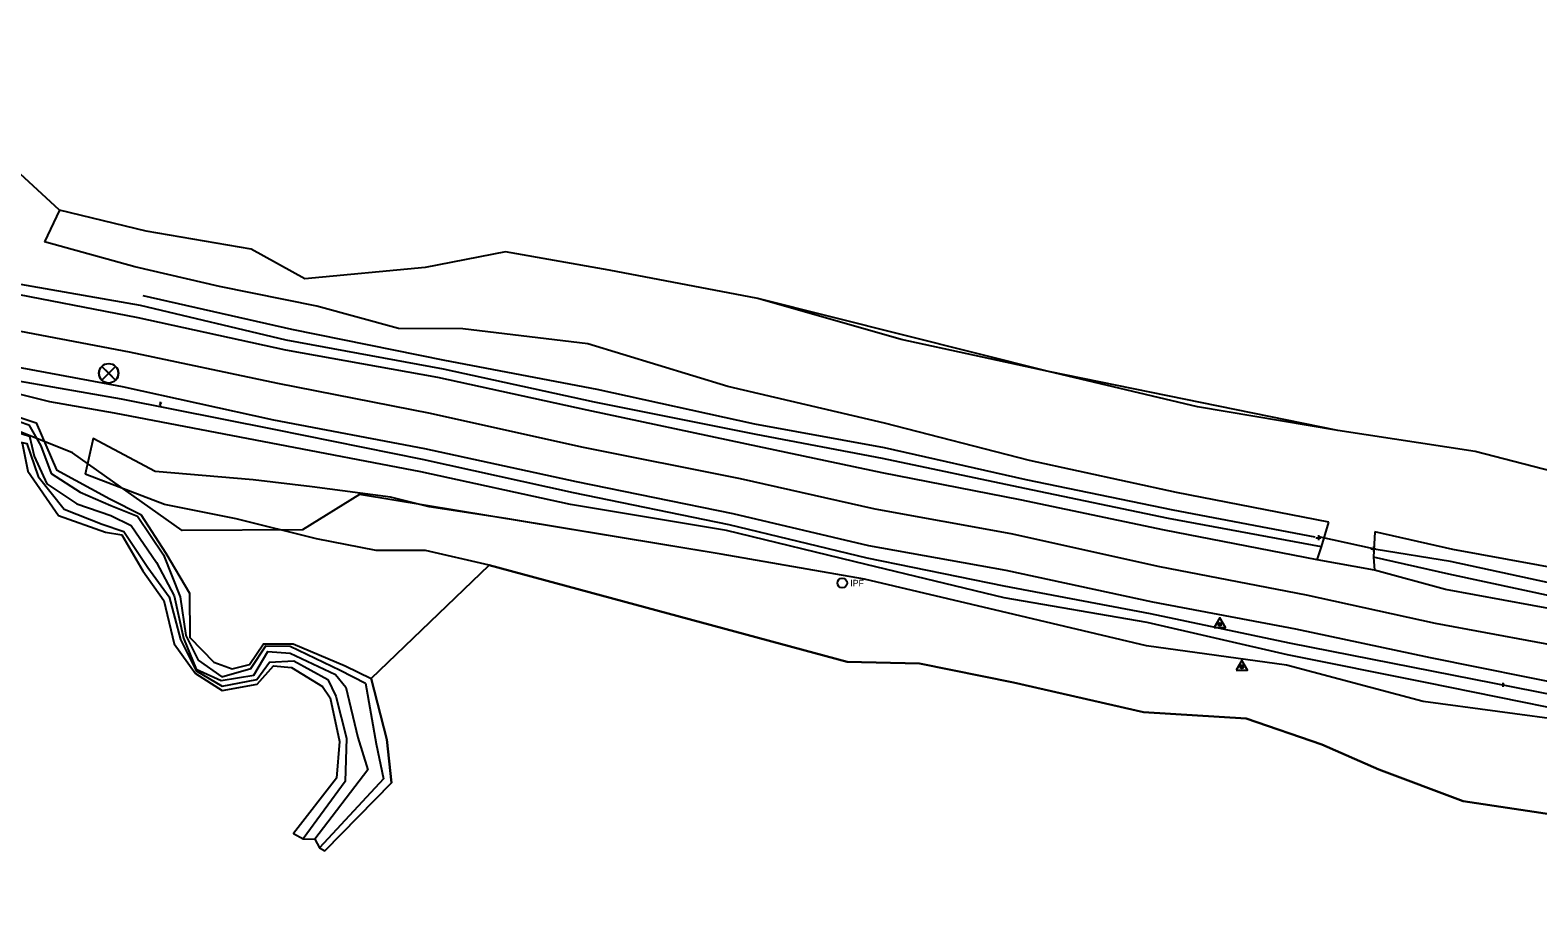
# Model space of a CAD drawing. Extents: x 1158469 to 1165378, y 609843 to 611748.
# Drawn here: x 1161265 to 1161728.7, y 610709.6 to 610983.5 of the extents above; entities that cross this region are included whole.
import ezdxf

# ---------------------------------------------------------------- set-up
doc = ezdxf.new("R2010")
doc.units = 0
for name, color, linetype in [('Exterior Boundary', 7, 'Continuous'), ('S_Control_Temp_Traverse', 7, 'Continuous'), ('S_Control_Traverse_Point', 7, 'Continuous'), ('S_Drainage_Culvert_Top', 7, 'Continuous'), ('S_Drainage_Ditch_Line', 7, 'Continuous'), ('S_Drainage_Invert', 7, 'Continuous'), ('S_Drainage_Waterway', 7, 'Continuous'), ('S_Ground_Elevation', 7, 'Continuous'), ('S_Ground_SpotElevation', 7, 'Continuous'), ('S_Property_IronPipeFound', 7, 'Continuous'), ('S_Roadway_Centerline', 7, 'Continuous'), ('S_Roadway_Edge_Pavement', 7, 'Continuous'), ('S_Roadway_Entr_Field_Wood', 7, 'Continuous'), ('S_Trees_TreeLine', 7, 'Continuous'), ('S_Utilities_UG_BoringLocation', 7, 'Continuous')]:
    doc.layers.add(name, color=color, linetype=linetype)

msp = doc.modelspace()

# ---------------------------------------------------------------- linework, layer by layer
at = {"layer": 'Exterior Boundary'}
for points in [[(1161754.22, 610842.36), (1161709.38, 610853.89), (1161667.17, 610860.36), (1161578.14, 610878.5), (1161488.83, 610900.92), (1161443.04, 610909.71), (1161411.18, 610915.31), (1161386.43, 610910.46), (1161349.48, 610906.98), (1161332.93, 610916.14), (1161300.61, 610921.61), (1161274, 610928.1), (1161260.61, 610940.47)], [(1161264.24, 610847.8), (1161273.73, 610834.24), (1161288.14, 610829.07), (1161293.19, 610828.3), (1161299.67, 610817.24), (1161306.08, 610808.09), (1161309.31, 610794.78), (1161315.87, 610785.65), (1161323.99, 610780.43), (1161334.82, 610782.31), (1161339.83, 610787.96), (1161345.36, 610787.46), (1161354.85, 610781.64), (1161357.27, 610778.1), (1161360.15, 610764.72), (1161359.24, 610753.43), (1161346, 610736.46), (1161348.98, 610734.8), (1161352.57, 610734.7), (1161353.93, 610731.98), (1161355.59, 610731.11), (1161376.09, 610752.03), (1161374.73, 610765.32), (1161369.82, 610784.14), (1161406.17, 610818.99), (1161516.3, 610789.17), (1161538.56, 610788.68), (1161567.46, 610782.86), (1161607.39, 610773.7), (1161638.99, 610771.82), (1161662.23, 610763.76), (1161679.82, 610756.1), (1161705.72, 610746.36), (1161737.12, 610741.7)]]:
    msp.add_lwpolyline(points, dxfattribs=at)
at = {"layer": 'S_Control_Temp_Traverse'}
for p, q in [((1161637.53, 610787.65), (1161637.78, 610787.65)), ((1161637.65, 610787.77), (1161637.65, 610787.52))]:
    msp.add_line(p, q, dxfattribs=at)
msp.add_lwpolyline([(1161635.92, 610786.65), (1161639.38, 610786.65), (1161637.65, 610789.65)], close=True, dxfattribs=at)
msp.add_circle((1161637.65, 610787.65), 0.5, dxfattribs=at)
at = {"layer": 'S_Control_Traverse_Point'}
for p, q in [((1161630.73, 610800.75), (1161630.98, 610800.75)), ((1161630.85, 610800.87), (1161630.85, 610800.62))]:
    msp.add_line(p, q, dxfattribs=at)
msp.add_lwpolyline([(1161629.12, 610799.75), (1161632.58, 610799.75), (1161630.85, 610802.75)], close=True, dxfattribs=at)
msp.add_circle((1161630.85, 610800.75), 0.5, dxfattribs=at)
at = {"layer": 'S_Drainage_Culvert_Top'}
msp.add_lwpolyline([(1161678.1, 610823.99), (1161661.34, 610827.65)], dxfattribs=at)
at = {"layer": 'S_Drainage_Ditch_Line'}
for points in [[(1161240.49, 610874.37), (1161240.56, 610869.57), (1161246.38, 610861.53), (1161256.4, 610861.31), (1161264.81, 610858.62), (1161266.17, 610852.48), (1161270.08, 610844), (1161279.35, 610837.83), (1161289.8, 610834.22), (1161296.09, 610831.16), (1161303.82, 610819.81), (1161309.31, 610809.5), (1161312.11, 610796.45), (1161315.99, 610787.01), (1161323.7, 610783.5), (1161333.78, 610785.14), (1161338.11, 610792.4), (1161344.91, 610791.9), (1161358.91, 610785.33)], [(1161362.12, 610781.47), (1161365.74, 610765.98), (1161368.83, 610756.03), (1161352.57, 610734.7)], [(1161358.91, 610785.33), (1161362.12, 610781.47)]]:
    msp.add_lwpolyline(points, dxfattribs=at)
at = {"layer": 'S_Drainage_Invert'}
for p, q in [((1161661.18, 610828.14), (1161661.18, 610826.64)), ((1161660.43, 610827.39), (1161661.93, 610827.39)), ((1161677.37, 610823.94), (1161678.87, 610823.94)), ((1161678.12, 610824.69), (1161678.12, 610823.19))]:
    msp.add_line(p, q, dxfattribs=at)
at = {"layer": 'S_Drainage_Waterway'}
for points in [[(1161241.67, 610874.19), (1161242.6, 610872.08), (1161249.22, 610866.27), (1161251.97, 610864.37), (1161258.63, 610864.13), (1161264.58, 610862.05), (1161268.3, 610855.69), (1161271.43, 610847.12), (1161280.38, 610841.38), (1161289.78, 610837.31), (1161298.01, 610833.99), (1161305.99, 610822.11), (1161311.15, 610809.24), (1161312.89, 610797.29), (1161316.7, 610789.69), (1161323.91, 610784.64), (1161332.81, 610787.12), (1161337.5, 610794.15), (1161344.91, 610794.02), (1161360.33, 610786.66)], [(1161236.73, 610873.49), (1161231.05, 610865.68), (1161230.05, 610852.4), (1161238.89, 610845.87), (1161249.62, 610853.15), (1161253.15, 610858.65), (1161263.99, 610856.33), (1161267.43, 610846.26), (1161275.39, 610836.13), (1161287.11, 610831.52), (1161293.84, 610829.29), (1161301.12, 610818.22), (1161307.71, 610809.22), (1161311.17, 610796.1), (1161316.07, 610786.42), (1161324.07, 610781.74), (1161334.71, 610783.77), (1161338.57, 610789.12), (1161346.06, 610789.51), (1161356.52, 610783.79)], [(1161360.33, 610786.66), (1161368.09, 610782.69)], [(1161368.09, 610782.69), (1161371.41, 610764.01), (1161373.64, 610753.23), (1161353.93, 610731.98)], [(1161356.52, 610783.79), (1161359.01, 610778.62)], [(1161359.01, 610778.62), (1161362.25, 610765.77), (1161361.86, 610752.43), (1161348.98, 610734.8)]]:
    msp.add_lwpolyline(points, dxfattribs=at)
at = {"layer": 'S_Ground_Elevation'}
for points in [[(1161662.12, 610824.6), (1161615.06, 610833.28), (1161570.93, 610842.51), (1161527.13, 610851.74), (1161488.26, 610859.12), (1161438.51, 610869.06), (1161392.1, 610879.17), (1161343.75, 610888.14), (1161298.92, 610898.79), (1161253.81, 610906.66), (1161217.92, 610914.01), (1161165.93, 610924.97), (1161116.75, 610934.27), (1161070.84, 610943.29), (1161018.86, 610953.77), (1160967.67, 610963.93), (1160913.31, 610974.22), (1160868.61, 610983.47)], [(1161790.92, 610767.7), (1161652.32, 610794.96), (1161609.52, 610803.98), (1161564.52, 610812.47), (1161522.37, 610821.13), (1161479.95, 610831.35), (1161432.13, 610841.23), (1161385.7, 610851.45), (1161340.05, 610860.71), (1161293.11, 610869.99), (1161250.75, 610877.37), (1161240.69, 610879.27), (1161216.11, 610885.09), (1161159.96, 610896.24), (1161111.51, 610906.19), (1161066.23, 610915.77), (1161015.8, 610925.93), (1160960.56, 610937.24), (1160907.14, 610946.59), (1160863.4, 610954.65)], [(1161754.22, 610842.36), (1161709.38, 610853.89), (1161667.17, 610860.36), (1161624.05, 610867.65), (1161578.14, 610878.5), (1161532.89, 610888.32), (1161488.83, 610900.92), (1161443.04, 610909.71), (1161411.18, 610915.31), (1161386.43, 610910.46), (1161349.48, 610906.98), (1161332.93, 610916.14), (1161300.61, 610921.61), (1161274, 610928.1), (1161269.34, 610918.39)], [(1161664.39, 610832.2), (1161617.51, 610841.34), (1161572.32, 610851.08), (1161527.76, 610862.6), (1161479.58, 610873.9), (1161436.47, 610886.98), (1161398.01, 610891.58), (1161378.28, 610891.77), (1161353.14, 610898.64), (1161323.21, 610904.64), (1161297.19, 610910.71), (1161269.34, 610918.39)], [(1161660.16, 610827.58), (1161616.5, 610835.81), (1161571.29, 610845.22), (1161527.78, 610855.04), (1161487.82, 610862.27), (1161439.38, 610872.93), (1161392.54, 610881.93), (1161345.45, 610891.42), (1161299.73, 610901.82)], [(1161738.64, 610773.86), (1161694.09, 610782.91), (1161651.67, 610791.38), (1161608.53, 610801.35), (1161564.59, 610808.93), (1161522.13, 610819.16), (1161479.19, 610829.62), (1161431.14, 610837.59), (1161385.12, 610847.66), (1161339.14, 610856.48), (1161290.9, 610865.68), (1161270.98, 610869.16), (1161250.36, 610874.26)], [(1161256.85, 610865.96), (1161266.85, 610862.75), (1161273.06, 610848.21), (1161289.46, 610839.3), (1161299.04, 610834.49), (1161306.69, 610822.59), (1161313.99, 610810.35), (1161314.13, 610796.73), (1161321.42, 610789.12), (1161327.13, 610787.06), (1161332.4, 610788.39), (1161336.74, 610794.78), (1161345.85, 610794.8), (1161361.85, 610788.01)], [(1161254.29, 610857.8), (1161262.53, 610856.53), (1161264.24, 610847.8), (1161273.73, 610834.24), (1161288.14, 610829.07), (1161293.19, 610828.3), (1161299.67, 610817.24), (1161306.08, 610808.09), (1161309.31, 610794.78), (1161315.87, 610785.65), (1161323.99, 610780.43), (1161334.82, 610782.31), (1161339.83, 610787.96), (1161345.36, 610787.46), (1161354.85, 610781.64)], [(1161739.1, 610770.82), (1161693.43, 610777.05), (1161651.4, 610788.18), (1161608.37, 610794.12), (1161563.73, 610804.71), (1161521.61, 610814.64), (1161477.5, 610822.28), (1161411.23, 610833.32), (1161387.71, 610836.93), (1161375.8, 610839.85), (1161351.69, 610843.04), (1161333.57, 610845.2), (1161303.44, 610847.76), (1161284.38, 610857.9), (1161281.94, 610846.96)], [(1161737.12, 610741.7), (1161705.72, 610746.36), (1161679.82, 610756.1), (1161662.23, 610763.76), (1161638.99, 610771.82), (1161607.39, 610773.7), (1161567.46, 610782.86), (1161538.56, 610788.68), (1161516.3, 610789.17), (1161406.17, 610818.99), (1161386.62, 610823.41), (1161371.44, 610823.48), (1161353.05, 610827.06), (1161328.35, 610833.24), (1161306.34, 610837.56), (1161281.94, 610846.96)], [(1162176.94, 610718.99), (1162154.3, 610725.45), (1162122.66, 610730.68), (1162100.37, 610736.98), (1162064.07, 610746.77), (1162020.81, 610756.65), (1161976.49, 610766.64), (1161937.43, 610774.41), (1161890.08, 610785.11), (1161843.21, 610795.95), (1161799.82, 610805.26), (1161745.66, 610815.83), (1161702.56, 610823.76), (1161678.56, 610829.17)], [(1162173.47, 610711.86), (1162149, 610718.48), (1162122.21, 610726.76), (1162100.02, 610731.86), (1162064.02, 610740.9), (1162020.75, 610751.91), (1161972.79, 610763.01), (1161936.37, 610770.61), (1161888.76, 610780.31), (1161843.43, 610789.92), (1161797.69, 610799.78), (1161744.92, 610810.72), (1161701.84, 610820.1), (1161678.95, 610823.78)], [(1162174.84, 610709.56), (1162148.15, 610714.91), (1162120.75, 610722.62), (1162099.83, 610728.68), (1162062.29, 610737.52), (1162019.65, 610748.06), (1161971.57, 610758.62), (1161935.32, 610767.71), (1161886.75, 610776.61), (1161843.46, 610787.24), (1161796.67, 610796.22), (1161745.21, 610806.74), (1161701.32, 610816.18), (1161678.12, 610821.37)], [(1161361.85, 610788.01), (1161369.82, 610784.14)], [(1161354.85, 610781.64), (1161357.27, 610778.1)], [(1161369.82, 610784.14), (1161374.73, 610765.32), (1161376.09, 610752.03), (1161355.59, 610731.11)], [(1161357.27, 610778.1), (1161360.15, 610764.72), (1161359.24, 610753.43), (1161346, 610736.46)]]:
    msp.add_lwpolyline(points, dxfattribs=at)
at = {"layer": 'S_Ground_SpotElevation'}
for p, q in [((1161304.79, 610868.95), (1161305.31, 610868.95)), ((1161305.31, 610868.95), (1161304.79, 610868.17)), ((1161304.79, 610868.17), (1161305.31, 610868.17)), ((1161304.89, 610868.56), (1161305.21, 610868.56)), ((1161717.76, 610782.58), (1161718.28, 610782.58)), ((1161718.28, 610782.58), (1161717.76, 610781.8)), ((1161717.76, 610781.8), (1161718.28, 610781.8)), ((1161717.86, 610782.19), (1161718.18, 610782.19))]:
    msp.add_line(p, q, dxfattribs=at)
at = {"layer": 'S_Property_IronPipeFound'}
msp.add_circle((1161514.74, 610813.44), 1.5, dxfattribs=at)
at = {"layer": 'S_Roadway_Centerline'}
msp.add_lwpolyline([(1161743.66, 610792.44), (1161697.24, 610801), (1161657.49, 610809.7), (1161612.39, 610818.39), (1161566.66, 610828.55), (1161524.89, 610836.19), (1161483.49, 610845.51), (1161434.62, 610855.28), (1161388.07, 610865.57), (1161341.11, 610874.84), (1161295.49, 610884.43), (1161253.43, 610892.43), (1161218.76, 610899.55), (1161162.27, 610911.37), (1161115.16, 610920.09), (1161068.85, 610929.83), (1161017.39, 610939.8), (1160963.84, 610950.14), (1160910.37, 610960.45), (1160866.37, 610969.58)], dxfattribs=at)
at = {"layer": 'S_Roadway_Edge_Pavement'}
for points in [[(1161744.93, 610803.31), (1161700.24, 610811.41), (1161678.48, 610817.43), (1161660.83, 610820.55), (1161613.91, 610829.7), (1161569.45, 610839.01), (1161527.05, 610847.32), (1161485.42, 610856.2), (1161436.3, 610866.64), (1161390.4, 610876.69), (1161343.58, 610885.03), (1161298.18, 610894.97), (1161254.68, 610903.4), (1161215.45, 610911.17), (1161163.61, 610921.91), (1161116.79, 610931.2), (1161070.48, 610940.63), (1161018.49, 610950.84), (1160967.14, 610960.62), (1160913.29, 610970.79), (1160867.74, 610980.12)], [(1161740.45, 610781.47), (1161695.63, 610790.49), (1161654.24, 610799.29), (1161610.23, 610807.59), (1161565.17, 610817.26), (1161522.94, 610824.91), (1161481.15, 610834.77), (1161433.01, 610844.57), (1161386.34, 610854.75), (1161339.96, 610863.58), (1161293.37, 610873.79), (1161251.96, 610881.47), (1161216.2, 610888.49), (1161160.59, 610900.13), (1161112.16, 610910.04), (1161066.23, 610919.03), (1161016.72, 610928.68), (1160961.87, 610940.1), (1160907.69, 610949.83), (1160864.23, 610958.56)]]:
    msp.add_lwpolyline(points, dxfattribs=at)
at = {"layer": 'S_Roadway_Entr_Field_Wood'}
for points in [[(1161660.83, 610820.55), (1161662.12, 610824.6), (1161664.39, 610832.2)], [(1161678.56, 610829.17), (1161678.35, 610825.44), (1161678.12, 610821.37), (1161678.48, 610817.43)]]:
    msp.add_lwpolyline(points, dxfattribs=at)
at = {"layer": 'S_Trees_TreeLine'}
for points in [[(1161398.01, 610891.58), (1161378.28, 610891.77)], [(1161366.29, 610840.69), (1161348.76, 610829.8), (1161311.69, 610829.63), (1161277.95, 610853.53), (1161243.36, 610867.29)], [(1161477.5, 610822.28), (1161366.29, 610840.69)], [(1161651.4, 610788.18), (1161608.37, 610794.12), (1161563.73, 610804.71), (1161521.61, 610814.64), (1161477.5, 610822.28)]]:
    msp.add_lwpolyline(points, dxfattribs=at)
at = {"layer": 'S_Utilities_UG_BoringLocation'}
for p, q in [((1161287.01, 610880.08), (1161291.25, 610875.84)), ((1161287.01, 610875.84), (1161291.25, 610880.08))]:
    msp.add_line(p, q, dxfattribs=at)
for points in [[(1161287.01, 610875.84), (1161289.13, 610877.96), (1161287.01, 610880.08)], [(1161291.25, 610880.08), (1161289.13, 610877.96), (1161291.25, 610875.84)]]:
    msp.add_lwpolyline(points, dxfattribs=at)
msp.add_circle((1161289.13, 610877.96), 3, dxfattribs=at)
for start, end in [(135, 225), (315, 45)]:
    msp.add_arc((1161289.13, 610877.96), 3, start, end, dxfattribs=at)

# ---------------------------------------------------------------- texts
at = {"layer": 'S_Property_IronPipeFound'}
msp.add_text('IPF', height=2, dxfattribs=at).set_placement((1161517.24, 610812.44))

doc.saveas('drawing.dxf')
